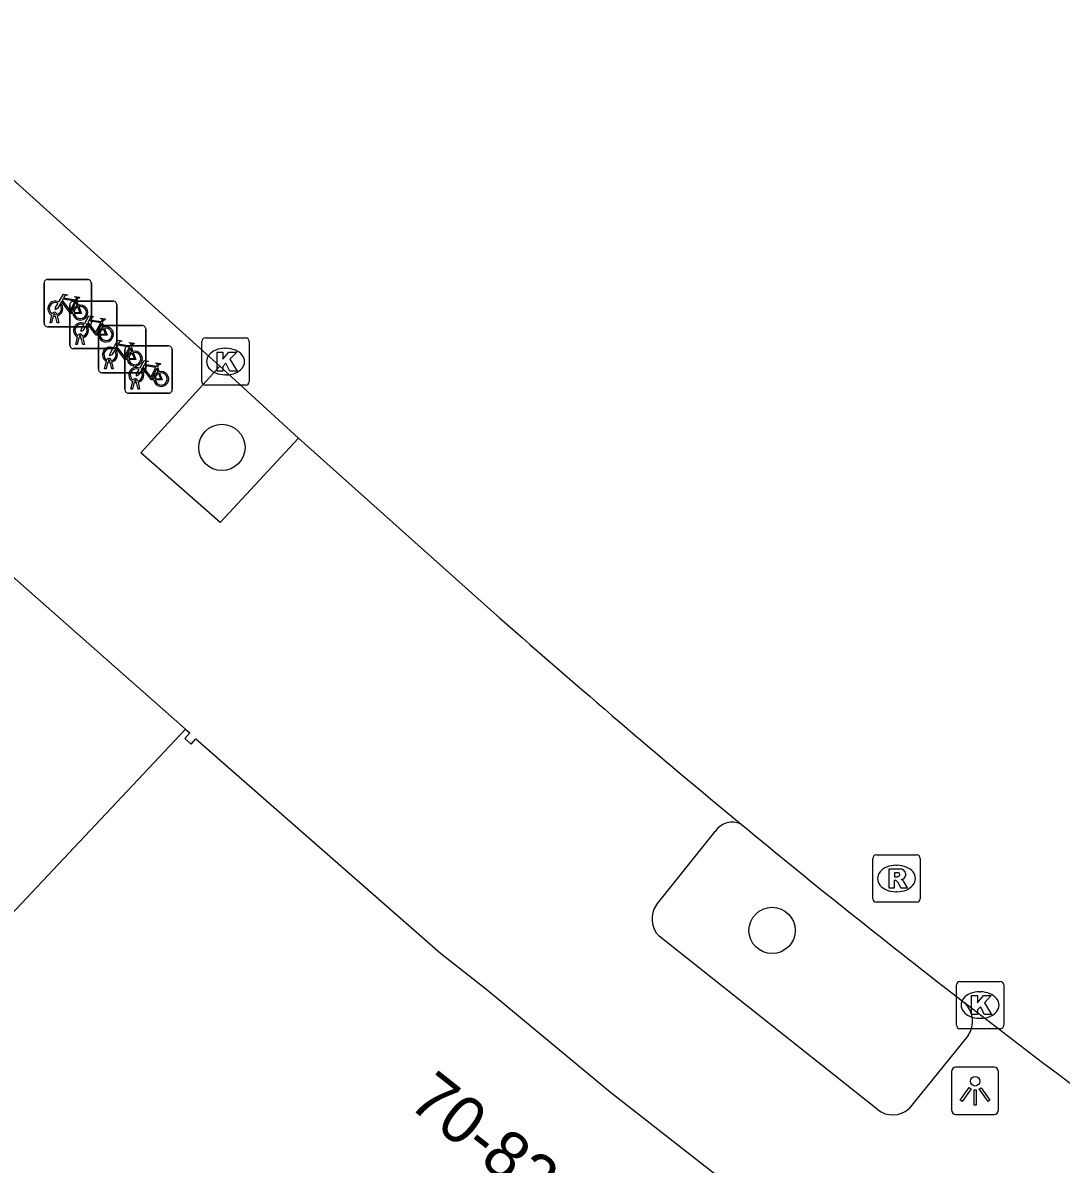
# Model space of a CAD drawing. Extents: x 161801 to 162379, y 382315 to 382832.
# Drawn here: x 162065.58 to 162087.53, y 382693.58 to 382717.71 of the extents above; entities that cross this region are included whole.
import ezdxf

# ---------------------------------------------------------------- set-up
doc = ezdxf.new("R2010")
doc.units = 0
for name, color, linetype in [('IMGEO_Boom', 7, 'Continuous'), ('IMGEO_Fietsenrek', 7, 'Continuous'), ('IMGEO_Kolk', 7, 'Continuous'), ('IMGEO_Lichtpunt', 7, 'Continuous'), ('IMGEO_Pand', 7, 'Continuous'), ('IMGEO_Pand_nummerreeks', 7, 'Continuous'), ('IMGEO_Rijbaan_lokaal_open', 7, 'Continuous'), ('IMGEO_Rioolput', 7, 'Continuous'), ('IMGEO_Voetpad_open', 7, 'Continuous')]:
    doc.layers.add(name, color=color, linetype=linetype)

msp = doc.modelspace()

# ---------------------------------------------------------------- linework, layer by layer
at = {"layer": 'IMGEO_Boom'}
for centre in [(162069.791, 382708.734), (162081.418, 382698.521)]:
    msp.add_circle(centre, 0.489, dxfattribs=at)
at = {"layer": 'IMGEO_Fietsenrek'}
for p, q in [((162066.107, 382712.283), (162066.948, 382712.283)), ((162066.948, 382712.283), (162066.107, 382712.283)), ((162066.032, 382711.358), (162066.032, 382712.199)), ((162066.032, 382712.199), (162066.032, 382711.358)), ((162067.032, 382712.208), (162067.032, 382711.367)), ((162067.032, 382711.367), (162067.032, 382712.208)), ((162066.649, 382711.822), (162067.49, 382711.822)), ((162067.49, 382711.822), (162066.649, 382711.822)), ((162066.719, 382711.832), (162066.755, 382711.737)), ((162066.159, 382711.367), (162066.198, 382711.527)), ((162066.27, 382711.539), (162066.269, 382711.543)), ((162066.301, 382711.55), (162066.302, 382711.543)), ((162066.574, 382710.897), (162066.574, 382711.738)), ((162066.574, 382711.738), (162066.574, 382710.897)), ((162067.574, 382711.747), (162067.574, 382710.906)), ((162067.574, 382710.906), (162067.574, 382711.747)), ((162066.957, 382711.283), (162066.116, 382711.283)), ((162066.116, 382711.283), (162066.957, 382711.283)), ((162066.193, 382711.367), (162066.159, 382711.367)), ((162066.228, 382711.515), (162066.193, 382711.367)), ((162066.311, 382711.367), (162066.277, 382711.509)), ((162066.309, 382711.513), (162066.344, 382711.367)), ((162066.344, 382711.367), (162066.311, 382711.367)), ((162067.259, 382711.309), (162068.1, 382711.309)), ((162068.1, 382711.309), (162067.259, 382711.309)), ((162067.261, 382711.371), (162067.297, 382711.276)), ((162066.701, 382710.906), (162066.74, 382711.066)), ((162066.77, 382711.054), (162066.735, 382710.906)), ((162066.812, 382711.078), (162066.811, 382711.082)), ((162066.853, 382710.906), (162066.819, 382711.048)), ((162066.843, 382711.089), (162066.844, 382711.082)), ((162066.851, 382711.052), (162066.886, 382710.906)), ((162067.184, 382710.384), (162067.184, 382711.225)), ((162067.184, 382711.225), (162067.184, 382710.384)), ((162068.184, 382711.234), (162068.184, 382710.393)), ((162068.184, 382710.393), (162068.184, 382711.234)), ((162067.499, 382710.822), (162066.658, 382710.822)), ((162066.658, 382710.822), (162067.499, 382710.822)), ((162066.735, 382710.906), (162066.701, 382710.906)), ((162066.886, 382710.906), (162066.853, 382710.906)), ((162067.741, 382709.954), (162067.741, 382710.795)), ((162067.741, 382710.795), (162067.741, 382709.954)), ((162067.816, 382710.879), (162068.657, 382710.879)), ((162068.657, 382710.879), (162067.816, 382710.879)), ((162067.871, 382710.858), (162067.907, 382710.763)), ((162068.741, 382710.804), (162068.741, 382709.963)), ((162068.741, 382709.963), (162068.741, 382710.804)), ((162067.311, 382710.393), (162067.35, 382710.553)), ((162067.422, 382710.565), (162067.421, 382710.569)), ((162067.453, 382710.576), (162067.454, 382710.569)), ((162067.345, 382710.393), (162067.311, 382710.393)), ((162067.38, 382710.541), (162067.345, 382710.393)), ((162067.463, 382710.393), (162067.429, 382710.535)), ((162067.461, 382710.539), (162067.496, 382710.393)), ((162067.496, 382710.393), (162067.463, 382710.393)), ((162068.428, 382710.428), (162068.464, 382710.333)), ((162068.109, 382710.309), (162067.268, 382710.309)), ((162067.268, 382710.309), (162068.109, 382710.309)), ((162067.868, 382709.963), (162067.907, 382710.123)), ((162067.937, 382710.111), (162067.902, 382709.963)), ((162067.979, 382710.135), (162067.978, 382710.139)), ((162068.02, 382709.963), (162067.986, 382710.105)), ((162068.01, 382710.146), (162068.011, 382710.139)), ((162068.018, 382710.109), (162068.053, 382709.963)), ((162068.666, 382709.879), (162067.825, 382709.879)), ((162067.825, 382709.879), (162068.666, 382709.879)), ((162067.902, 382709.963), (162067.868, 382709.963)), ((162068.053, 382709.963), (162068.02, 382709.963))]:
    msp.add_line(p, q, dxfattribs=at)
for points in [[(162066.366, 382711.757), (162066.314, 382711.667), (162066.274, 382711.642), (162066.275, 382711.689), (162066.33, 382711.783)], [(162066.345, 382711.809), (162066.44, 382711.973), (162066.526, 382711.959), (162066.528, 382711.95), (162066.472, 382711.939), (162066.445, 382711.894), (162066.701, 382711.853)], [(162066.641, 382711.565), (162066.591, 382711.565), (162066.4, 382711.816), (162066.381, 382711.784)], [(162066.688, 382711.828), (162066.431, 382711.869), (162066.414, 382711.84), (162066.581, 382711.62), (162066.688, 382711.828)], [(162066.736, 382711.73), (162066.706, 382711.807), (162066.597, 382711.589), (162066.64, 382711.589)], [(162066.701, 382711.853), (162066.726, 382711.902), (162066.72, 382711.906), (162066.697, 382711.91), (162066.685, 382711.917), (162066.684, 382711.92), (162066.686, 382711.925), (162066.781, 382711.91), (162066.783, 382711.9), (162066.773, 382711.887), (162066.761, 382711.881), (162066.747, 382711.887), (162066.719, 382711.832)], [(162066.67, 382711.589), (162066.79, 382711.588), (162066.746, 382711.702)], [(162066.766, 382711.709), (162066.821, 382711.564), (162066.671, 382711.564)], [(162066.908, 382711.296), (162066.856, 382711.206), (162066.816, 382711.181), (162066.817, 382711.228), (162066.872, 382711.322)], [(162066.887, 382711.348), (162066.982, 382711.512), (162067.068, 382711.498), (162067.07, 382711.489), (162067.014, 382711.478), (162066.987, 382711.433), (162067.243, 382711.392)], [(162067.183, 382711.104), (162067.133, 382711.104), (162066.942, 382711.355), (162066.923, 382711.323)], [(162067.23, 382711.367), (162066.973, 382711.408), (162066.956, 382711.379), (162067.123, 382711.159), (162067.23, 382711.367)], [(162067.278, 382711.269), (162067.248, 382711.346), (162067.139, 382711.128), (162067.182, 382711.128)], [(162067.243, 382711.392), (162067.268, 382711.441), (162067.262, 382711.445), (162067.239, 382711.449), (162067.227, 382711.456), (162067.226, 382711.459), (162067.228, 382711.464), (162067.323, 382711.449), (162067.325, 382711.439), (162067.315, 382711.426), (162067.303, 382711.42), (162067.289, 382711.426), (162067.261, 382711.371)], [(162067.212, 382711.128), (162067.332, 382711.127), (162067.288, 382711.241)], [(162067.308, 382711.248), (162067.363, 382711.103), (162067.213, 382711.103)], [(162067.518, 382710.783), (162067.466, 382710.693), (162067.426, 382710.668), (162067.427, 382710.715), (162067.482, 382710.809)], [(162067.497, 382710.835), (162067.592, 382710.999), (162067.678, 382710.985), (162067.68, 382710.976), (162067.624, 382710.965), (162067.597, 382710.92), (162067.853, 382710.879)], [(162067.793, 382710.591), (162067.743, 382710.591), (162067.552, 382710.842), (162067.533, 382710.81)], [(162067.84, 382710.854), (162067.583, 382710.895), (162067.566, 382710.866), (162067.733, 382710.646), (162067.84, 382710.854)], [(162067.888, 382710.756), (162067.858, 382710.833), (162067.749, 382710.615), (162067.792, 382710.615)], [(162067.853, 382710.879), (162067.878, 382710.928), (162067.872, 382710.932), (162067.849, 382710.936), (162067.837, 382710.943), (162067.836, 382710.946), (162067.838, 382710.951), (162067.933, 382710.936), (162067.935, 382710.926), (162067.925, 382710.913), (162067.913, 382710.907), (162067.899, 382710.913), (162067.871, 382710.858)], [(162067.822, 382710.615), (162067.942, 382710.614), (162067.898, 382710.728)], [(162067.918, 382710.735), (162067.973, 382710.59), (162067.823, 382710.59)], [(162068.054, 382710.405), (162068.149, 382710.569), (162068.235, 382710.555), (162068.237, 382710.546), (162068.181, 382710.535), (162068.154, 382710.49), (162068.41, 382710.449)], [(162068.075, 382710.353), (162068.023, 382710.263), (162067.983, 382710.238), (162067.984, 382710.285), (162068.039, 382710.379)], [(162068.35, 382710.161), (162068.3, 382710.161), (162068.109, 382710.412), (162068.09, 382710.38)], [(162068.397, 382710.424), (162068.14, 382710.465), (162068.123, 382710.436), (162068.29, 382710.216), (162068.397, 382710.424)], [(162068.445, 382710.326), (162068.415, 382710.403), (162068.306, 382710.185), (162068.349, 382710.185)], [(162068.41, 382710.449), (162068.435, 382710.498), (162068.429, 382710.502), (162068.406, 382710.506), (162068.394, 382710.513), (162068.393, 382710.516), (162068.395, 382710.521), (162068.49, 382710.506), (162068.492, 382710.496), (162068.482, 382710.483), (162068.47, 382710.477), (162068.456, 382710.483), (162068.428, 382710.428)], [(162068.379, 382710.185), (162068.499, 382710.184), (162068.455, 382710.298)], [(162068.475, 382710.305), (162068.53, 382710.16), (162068.38, 382710.16)]]:
    msp.add_lwpolyline(points, dxfattribs=at)
for centre, radius, start, end in [((162066.11, 382712.205), 0.0779, 92.4484, 184.2845), ((162066.11, 382712.205), 0.0779, 92.4484, 184.2845), ((162066.954, 382712.205), 0.0779, 2.4484, 94.2845), ((162066.954, 382712.205), 0.0779, 2.4484, 94.2845), ((162066.272, 382711.668), 0.159, 62.6766, 242.1369), ((162066.272, 382711.668), 0.129, 63.3192, 238.903), ((162066.272, 382711.668), 0.159, 283.5766, 46.6042), ((162066.652, 382711.744), 0.0779, 92.4484, 184.2845), ((162066.652, 382711.744), 0.0779, 92.4484, 184.2845), ((162067.496, 382711.744), 0.0779, 2.4484, 94.2845), ((162067.496, 382711.744), 0.0779, 2.4484, 94.2845), ((162066.252, 382711.539), 0.0499, 12.8025, 158.6934), ((162066.252, 382711.539), 0.0174, 12.8025, 163.4502), ((162066.272, 382711.668), 0.129, 253.415, 269.0204), ((162066.272, 382711.668), 0.129, 283.6043, 43.4302), ((162066.799, 382711.584), 0.159, 113.3408, 178.3217), ((162066.799, 382711.584), 0.159, 187.0065, 105.7708), ((162066.799, 382711.584), 0.129, 113.923, 177.9556), ((162066.799, 382711.584), 0.129, 188.6715, 104.5883), ((162066.11, 382711.361), 0.0779, 182.4484, 274.2845), ((162066.11, 382711.361), 0.0779, 182.4484, 274.2845), ((162066.272, 382711.668), 0.159, 253.9967, 271.7867), ((162066.814, 382711.207), 0.159, 62.6766, 242.1369), ((162066.814, 382711.207), 0.129, 63.3192, 238.903), ((162066.814, 382711.207), 0.129, 283.6043, 43.4302), ((162066.814, 382711.207), 0.159, 283.5766, 46.6042), ((162066.954, 382711.361), 0.0779, 272.4484, 4.2845), ((162066.954, 382711.361), 0.0779, 272.4484, 4.2845), ((162067.341, 382711.123), 0.159, 187.0065, 105.7708), ((162067.262, 382711.231), 0.0779, 92.4484, 184.2845), ((162067.262, 382711.231), 0.0779, 92.4484, 184.2845), ((162068.106, 382711.231), 0.0779, 2.4484, 94.2845), ((162068.106, 382711.231), 0.0779, 2.4484, 94.2845), ((162066.794, 382711.078), 0.0499, 12.8025, 158.6934), ((162066.814, 382711.207), 0.159, 253.9967, 271.7867), ((162066.794, 382711.078), 0.0174, 12.8025, 163.4502), ((162066.814, 382711.207), 0.129, 253.415, 269.0204), ((162067.341, 382711.123), 0.159, 113.3408, 178.3217), ((162067.341, 382711.123), 0.129, 113.923, 177.9556), ((162067.341, 382711.123), 0.129, 188.6715, 104.5883), ((162066.652, 382710.9), 0.0779, 182.4484, 274.2845), ((162066.652, 382710.9), 0.0779, 182.4484, 274.2845), ((162067.424, 382710.694), 0.159, 62.6766, 242.1369), ((162067.424, 382710.694), 0.129, 63.3192, 238.903), ((162067.424, 382710.694), 0.159, 283.5766, 46.6042), ((162067.496, 382710.9), 0.0779, 272.4484, 4.2845), ((162067.496, 382710.9), 0.0779, 272.4484, 4.2845), ((162067.819, 382710.801), 0.0779, 92.4484, 184.2845), ((162067.819, 382710.801), 0.0779, 92.4484, 184.2845), ((162068.663, 382710.801), 0.0779, 2.4484, 94.2845), ((162068.663, 382710.801), 0.0779, 2.4484, 94.2845), ((162067.404, 382710.565), 0.0499, 12.8025, 158.6934), ((162067.404, 382710.565), 0.0174, 12.8025, 163.4502), ((162067.424, 382710.694), 0.129, 253.415, 269.0204), ((162067.424, 382710.694), 0.129, 283.6043, 43.4302), ((162067.951, 382710.61), 0.159, 113.3408, 178.3217), ((162067.951, 382710.61), 0.159, 187.0065, 105.7708), ((162067.951, 382710.61), 0.129, 113.923, 177.9556), ((162067.951, 382710.61), 0.129, 188.6715, 104.5883), ((162067.262, 382710.387), 0.0779, 182.4484, 274.2845), ((162067.262, 382710.387), 0.0779, 182.4484, 274.2845), ((162067.424, 382710.694), 0.159, 253.9967, 271.7867), ((162067.981, 382710.264), 0.159, 62.6766, 242.1369), ((162067.981, 382710.264), 0.129, 63.3192, 238.903), ((162067.981, 382710.264), 0.129, 283.6043, 43.4302), ((162067.981, 382710.264), 0.159, 283.5766, 46.6042), ((162068.106, 382710.387), 0.0779, 272.4484, 4.2845), ((162068.106, 382710.387), 0.0779, 272.4484, 4.2845), ((162068.508, 382710.18), 0.159, 113.3408, 178.3217), ((162068.508, 382710.18), 0.159, 187.0065, 105.7708), ((162067.961, 382710.135), 0.0499, 12.8025, 158.6934), ((162067.981, 382710.264), 0.159, 253.9967, 271.7867), ((162067.961, 382710.135), 0.0174, 12.8025, 163.4502), ((162067.981, 382710.264), 0.129, 253.415, 269.0204), ((162068.508, 382710.18), 0.129, 113.923, 177.9556), ((162068.508, 382710.18), 0.129, 188.6715, 104.5883), ((162067.819, 382709.957), 0.0779, 182.4484, 274.2845), ((162067.819, 382709.957), 0.0779, 182.4484, 274.2845), ((162068.663, 382709.957), 0.0779, 272.4484, 4.2845), ((162068.663, 382709.957), 0.0779, 272.4484, 4.2845)]:
    msp.add_arc(centre, radius, start, end, dxfattribs=at)
at = {"layer": 'IMGEO_Kolk'}
for p, q in [((162069.442, 382711.048), (162070.294, 382711.048)), ((162069.367, 382710.122), (162069.367, 382710.974)), ((162069.855, 382710.828), (162069.88, 382710.828)), ((162070.368, 382710.974), (162070.368, 382710.122)), ((162069.878, 382710.268), (162069.853, 382710.268)), ((162070.294, 382710.048), (162069.442, 382710.048)), ((162085.313, 382696.517), (162085.313, 382697.369)), ((162085.388, 382697.443), (162086.24, 382697.443)), ((162086.314, 382697.369), (162086.314, 382696.517)), ((162085.801, 382697.223), (162085.826, 382697.223)), ((162085.824, 382696.663), (162085.799, 382696.663)), ((162086.24, 382696.443), (162085.388, 382696.443))]:
    msp.add_line(p, q, dxfattribs=at)
for points in [[(162069.442, 382711.048), (162070.294, 382711.048)], [(162069.367, 382710.122), (162069.367, 382710.974)], [(162070.368, 382710.974), (162070.368, 382710.122)], [(162069.688, 382710.748), (162069.811, 382710.748), (162069.811, 382710.597), (162069.941, 382710.748), (162070.105, 382710.748), (162069.959, 382710.597), (162070.112, 382710.348), (162069.96, 382710.348), (162069.875, 382710.512), (162069.811, 382710.445), (162069.811, 382710.348), (162069.688, 382710.348), (162069.688, 382710.748)], [(162070.294, 382710.048), (162069.442, 382710.048)], [(162085.313, 382696.517), (162085.313, 382697.369)], [(162085.388, 382697.443), (162086.24, 382697.443)], [(162086.314, 382697.369), (162086.314, 382696.517)], [(162085.634, 382697.143), (162085.757, 382697.143), (162085.757, 382696.992), (162085.887, 382697.143), (162086.051, 382697.143), (162085.905, 382696.992), (162086.058, 382696.743), (162085.906, 382696.743), (162085.821, 382696.907), (162085.757, 382696.84), (162085.757, 382696.743), (162085.634, 382696.743), (162085.634, 382697.143)], [(162086.24, 382696.443), (162085.388, 382696.443)]]:
    msp.add_lwpolyline(points, dxfattribs=at)
for centre, start, end in [((162069.444, 382710.972), 91.552, 178.448), ((162069.444, 382710.972), 91.552, 178.448), ((162070.292, 382710.972), 1.552, 88.448), ((162070.292, 382710.972), 1.552, 88.448), ((162069.444, 382710.124), 181.552, 268.448), ((162069.444, 382710.124), 181.552, 268.448), ((162070.292, 382710.124), 271.552, 358.448), ((162070.292, 382710.124), 271.552, 358.448), ((162085.39, 382697.367), 91.552, 178.448), ((162085.39, 382697.367), 91.552, 178.448), ((162086.238, 382697.367), 1.552, 88.448), ((162086.238, 382697.367), 1.552, 88.448), ((162085.39, 382696.519), 181.552, 268.448), ((162085.39, 382696.519), 181.552, 268.448), ((162086.238, 382696.519), 271.552, 358.448), ((162086.238, 382696.519), 271.552, 358.448)]:
    msp.add_arc(centre, 0.0765, start, end, dxfattribs=at)
for centre, major_axis, ratio, start_param, end_param in [((162069.854, 382710.548), (-0.387, 0.002), 0.722429, 4.712389, 7.853982), ((162069.879, 382710.548), (-0.39, 0.002), 0.717154, 1.570796, 4.712389), ((162085.8, 382696.943), (-0.387, 0.002), 0.722429, 4.712389, 7.853982), ((162085.825, 382696.943), (-0.39, 0.002), 0.717154, 1.570796, 4.712389)]:
    msp.add_ellipse(centre, major_axis=major_axis, ratio=ratio, start_param=start_param, end_param=end_param, dxfattribs=at)
at = {"layer": 'IMGEO_Lichtpunt'}
for p, q in [((162086.112, 382695.629), (162085.304, 382695.629)), ((162086.112, 382695.629), (162085.304, 382695.629)), ((162085.21, 382695.534), (162085.21, 382694.727)), ((162085.21, 382695.534), (162085.21, 382694.727)), ((162086.206, 382694.727), (162086.206, 382695.534)), ((162086.206, 382694.727), (162086.206, 382695.534)), ((162085.304, 382694.633), (162086.112, 382694.633)), ((162085.304, 382694.633), (162086.112, 382694.633))]:
    msp.add_line(p, q, dxfattribs=at)
for points in [[(162085.584, 382695.198), (162085.623, 382695.17), (162085.435, 382694.908), (162085.397, 382694.935), (162085.584, 382695.198)], [(162085.686, 382695.15), (162085.733, 382695.15), (162085.733, 382694.828), (162085.686, 382694.828), (162085.686, 382695.15)], [(162085.796, 382695.17), (162085.834, 382695.197), (162086.021, 382694.935), (162085.982, 382694.907), (162085.796, 382695.17)]]:
    msp.add_lwpolyline(points, dxfattribs=at)
msp.add_circle((162085.709, 382695.332), 0.0994, dxfattribs=at)
for centre, start, end in [((162085.304, 382695.534), 90, 180), ((162085.304, 382695.534), 90, 180), ((162086.112, 382695.534), 0, 90), ((162086.112, 382695.534), 0, 90), ((162085.304, 382694.727), 180, 270), ((162085.304, 382694.727), 180, 270), ((162086.112, 382694.727), 270, 0), ((162086.112, 382694.727), 270, 360)]:
    msp.add_arc(centre, 0.0946, start, end, dxfattribs=at)
at = {"layer": 'IMGEO_Pand'}
for points in [[(162063.786, 382707.393), (162069.024, 382702.773)], [(162069.024, 382702.773), (162060.288, 382693.496)], [(162069.024, 382702.773), (162069.111, 382702.696), (162069.007, 382702.578), (162069.144, 382702.458), (162069.243, 382702.571), (162074.414, 382698.042), (162075.398, 382697.265), (162078.004, 382695.105), (162083.043, 382691.165), (162087.494, 382688.013)]]:
    msp.add_lwpolyline(points, dxfattribs=at)
at = {"layer": 'IMGEO_Rijbaan_lokaal_open'}
for points in [[(162061.695, 382717.709), (162069.75, 382710.451)], [(162069.75, 382710.451), (162071.409, 382708.931)], [(162071.409, 382708.931), (162075.668, 382705.123)]]:
    msp.add_lwpolyline(points, dxfattribs=at)
for centre, radius, start, end in [((162224.335, 382873.807), 224.847, 228.60922, 230.31794), ((162202.221, 382847.948), 190.826, 230.47021, 232.28423), ((162287.694, 382959.98), 331.738, 232.4433, 234.99566)]:
    msp.add_arc(centre, radius, start, end, dxfattribs=at)
at = {"layer": 'IMGEO_Rioolput'}
for p, q in [((162083.547, 382699.193), (162083.547, 382700.045)), ((162083.622, 382700.119), (162084.474, 382700.119)), ((162084.548, 382700.045), (162084.548, 382699.193)), ((162084.035, 382699.899), (162084.06, 382699.899)), ((162084.058, 382699.339), (162084.033, 382699.339)), ((162084.474, 382699.119), (162083.622, 382699.119))]:
    msp.add_line(p, q, dxfattribs=at)
for points in [[(162083.547, 382699.193), (162083.547, 382700.045)], [(162083.622, 382700.119), (162084.474, 382700.119)], [(162084.548, 382700.045), (162084.548, 382699.193)], [(162084.136, 382699.817), (162083.884, 382699.819), (162083.884, 382699.419)], [(162084.062, 382699.738), (162084.008, 382699.738), (162084.008, 382699.657)], [(162083.884, 382699.419), (162084.008, 382699.419), (162084.008, 382699.581), (162084.019, 382699.581)], [(162084.008, 382699.657), (162084.06, 382699.657)], [(162084.066, 382699.552), (162084.137, 382699.419), (162084.277, 382699.419), (162084.212, 382699.545)], [(162084.474, 382699.119), (162083.622, 382699.119)]]:
    msp.add_lwpolyline(points, dxfattribs=at)
for centre, radius, start, end in [((162083.624, 382700.043), 0.0765, 91.552, 178.448), ((162083.624, 382700.043), 0.0765, 91.552, 178.448), ((162084.472, 382700.043), 0.0765, 1.552, 88.448), ((162084.472, 382700.043), 0.0765, 1.552, 88.448), ((162084.068, 382699.642), 0.0964, 77.0061, 93.1865), ((162084.082, 382699.699), 0.0378, 276.6634, 79.6772), ((162084.135, 382699.707), 0.109, 350.3612, 89.416), ((162084.018, 382699.528), 0.0533, 26.0293, 88.6989), ((162084.044, 382699.846), 0.19, 274.7715, 282.9687), ((162084.133, 382699.707), 0.112, 277.5842, 350.9817), ((162084.117, 382699.492), 0.108, 29.5134, 73.7905), ((162083.624, 382699.195), 0.0765, 181.552, 268.448), ((162083.624, 382699.195), 0.0765, 181.552, 268.448), ((162084.472, 382699.195), 0.0765, 271.552, 358.448), ((162084.472, 382699.195), 0.0765, 271.552, 358.448)]:
    msp.add_arc(centre, radius, start, end, dxfattribs=at)
for centre, major_axis, ratio, start_param, end_param in [((162084.034, 382699.619), (-0.387, 0.002), 0.722429, 4.712389, 7.853982), ((162084.059, 382699.619), (-0.39, 0.002), 0.717154, 1.570796, 4.712389)]:
    msp.add_ellipse(centre, major_axis=major_axis, ratio=ratio, start_param=start_param, end_param=end_param, dxfattribs=at)
at = {"layer": 'IMGEO_Voetpad_open'}
for points in [[(162071.409, 382708.931), (162069.751, 382707.144), (162068.075, 382708.62), (162069.75, 382710.451)], [(162078.976, 382699.065), (162080.217, 382700.61)], [(162083.648, 382694.735), (162079.032, 382698.4)], [(162085.563, 382696.299), (162084.308, 382694.751)]]:
    msp.add_lwpolyline(points, dxfattribs=at)
for centre, radius, start, end in [((162080.574, 382700.394), 0.417, 62.8242, 148.8175), ((162079.396, 382698.766), 0.516, 144.5099, 225.1172), ((162085.117, 382696.6), 0.539, 325.9915, 46.9783), ((162083.969, 382695.129), 0.508, 230.8742, 311.9033)]:
    msp.add_arc(centre, radius, start, end, dxfattribs=at)

# ---------------------------------------------------------------- texts
at = {"layer": 'IMGEO_Pand_nummerreeks'}
msp.add_text('70-82A', height=1, rotation=321.6863, dxfattribs=at).set_placement((162073.695, 382694.818))

doc.saveas('drawing.dxf')
